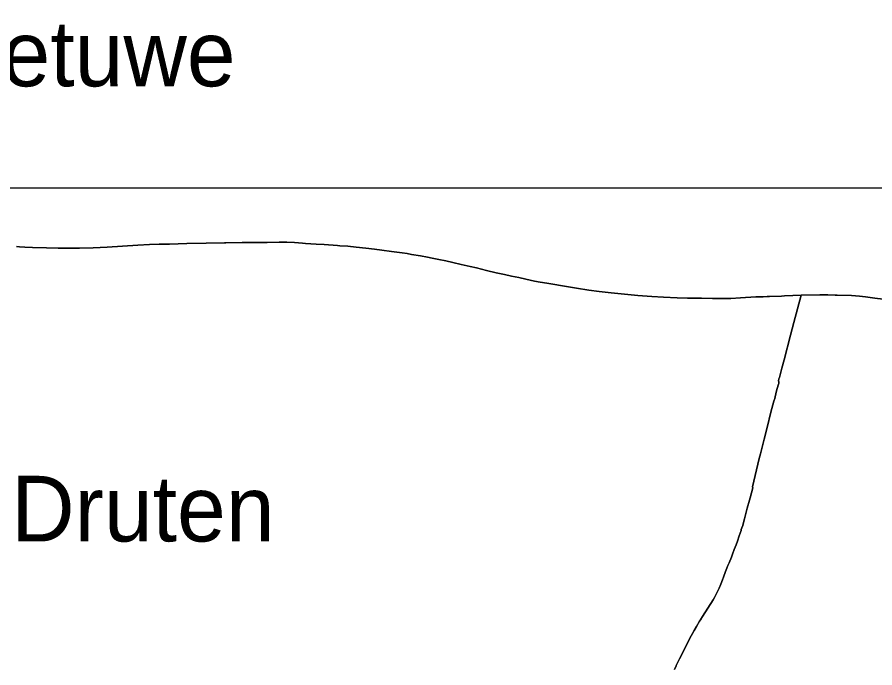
# Model space of a CAD drawing. Extents: x 113371 to 291721, y 393993 to 520143.
# Drawn here: x 169499 to 176035, y 431347 to 436303 of the extents above; entities that cross this region are included whole.
import ezdxf

# ---------------------------------------------------------------- set-up
doc = ezdxf.new("R2010")
doc.units = 0
for name, color, linetype in [('Boudingbox', 7, 'Continuous'), ('Default', 7, 'Continuous'), ('plaatsnamen', 7, 'Continuous')]:
    doc.layers.add(name, color=color, linetype=linetype)

msp = doc.modelspace()

# ---------------------------------------------------------------- linework, layer by layer
at = {"layer": 'Boudingbox'}
msp.add_line((177000, 435000), (164000, 435000), dxfattribs=at)
at = {"layer": 'Default'}
for points in [[(172504.745625, 434495.9625), (172471.995625, 434501.7225), (172433.555625, 434507.1525), (172350.655625, 434518.1225), (172278.425625, 434527.5125), (172221.665625, 434535.3625), (172156.345625, 434542.5625), (172082.175625, 434551.2025), (172019.735625, 434558.1425), (171958.345625, 434562.1025), (171939.345625, 434563.3225), (171838.765625, 434570.5125), (171778.715625, 434574.3425), (171697.205625, 434580.0125), (171674.285625, 434581.4725), (171612.385625, 434585.4125), (171554.745625, 434589.0725), (171495.255625, 434588.2825), (171403.815625, 434587.6825), (171361.415625, 434587.7225), (171212.845625, 434586.5725), (171089.845625, 434585.3025), (171078.245625, 434584.8525), (170938.375625, 434581.3825), (170791.285625, 434578.1325), (170660.135625, 434575.1825), (170581.985625, 434573.8525), (170506.225625, 434570.2825), (170418.085625, 434566.7525), (170185.095625, 434551.5725), (170077.115625, 434546.2025), (169974.555625, 434543.1825), (169811.185625, 434544.1725), (169721.305625, 434545.9225), (169615.485625, 434549.6925), (169557.505625, 434551.2625), (169515.485625, 434554.1825), (169493.465625, 434555.7025)], [(169493.465625, 434555.7025), (169515.485625, 434554.1825), (169557.505625, 434551.2625), (169615.485625, 434549.6925), (169721.305625, 434545.9225), (169811.185625, 434544.1725), (169974.555625, 434543.1825), (170077.115625, 434546.2025), (170185.095625, 434551.5725), (170418.085625, 434566.7525), (170506.225625, 434570.2825), (170581.985625, 434573.8525), (170660.135625, 434575.1825), (170791.285625, 434578.1325), (170938.375625, 434581.3825), (171078.245625, 434584.8525), (171089.845625, 434585.3025), (171212.845625, 434586.5725), (171361.415625, 434587.7225), (171403.815625, 434587.6825), (171495.255625, 434588.2825), (171554.745625, 434589.0725), (171612.385625, 434585.4125), (171674.285625, 434581.4725), (171697.205625, 434580.0125)], [(171697.205625, 434580.0125), (171778.715625, 434574.3425), (171838.765625, 434570.5125), (171939.345625, 434563.3225), (171958.345625, 434562.1025), (172019.735625, 434558.1425), (172082.175625, 434551.2025), (172156.345625, 434542.5625), (172221.665625, 434535.3625), (172278.425625, 434527.5125), (172350.655625, 434518.1225), (172433.555625, 434507.1525), (172471.995625, 434501.7225), (172504.745625, 434495.9625), (172573.835625, 434484.1625), (172626.265625, 434474.3525), (172662.475625, 434467.1225), (172712.205625, 434457.5925), (172765.095625, 434446.3025), (172817.985625, 434434.4025), (172882.745625, 434420.2025), (172906.485625, 434414.5725), (172952.025625, 434403.7925), (172999.065625, 434392.9025), (173076.765625, 434374.0125), (173150.555625, 434356.1325), (173212.755625, 434342.5125), (173265.655625, 434330.9125), (173321.995625, 434319.0425), (173376.395625, 434307.1525), (173441.455625, 434292.6525), (173485.475625, 434284.4325), (173536.605625, 434275.6325), (173582.185625, 434268.4225), (173653.715625, 434256.3825), (173760.935625, 434238.4925), (173856.465625, 434223.5925), (173935.505625, 434212.4425)], [(175010.355625, 434165.4825), (174937.215625, 434161.2925), (174923.275625, 434160.4925), (174882.065625, 434159.8325), (174798.225625, 434160.1125), (174714.375625, 434161.4425), (174606.525625, 434162.5025), (174528.685625, 434165.6125), (174424.895625, 434169.9525), (174334.745625, 434175.0025), (174229.605625, 434183.2225), (174128.225625, 434193.3625), (174026.085625, 434203.3625), (173935.505625, 434212.4425), (173856.465625, 434223.5925), (173760.935625, 434238.4925), (173653.715625, 434256.3825), (173582.185625, 434268.4225), (173536.605625, 434275.6325), (173485.475625, 434284.4325), (173441.455625, 434292.6525), (173376.395625, 434307.1525), (173321.995625, 434319.0425), (173265.655625, 434330.9125), (173212.755625, 434342.5125), (173150.555625, 434356.1325), (173076.765625, 434374.0125), (172999.065625, 434392.9025), (172952.025625, 434403.7925), (172906.485625, 434414.5725), (172882.745625, 434420.2025), (172817.985625, 434434.4025), (172765.095625, 434446.3025), (172712.205625, 434457.5925), (172662.475625, 434467.1225), (172626.265625, 434474.3525), (172573.835625, 434484.1625), (172504.745625, 434495.9625)], [(173935.505625, 434212.4425), (174026.085625, 434203.3625), (174128.225625, 434193.3625), (174229.605625, 434183.2225), (174334.745625, 434175.0025), (174424.895625, 434169.9525), (174528.685625, 434165.6125), (174606.525625, 434162.5025), (174714.375625, 434161.4425), (174798.225625, 434160.1125), (174882.065625, 434159.8325), (174923.275625, 434160.4925), (174937.215625, 434161.2925), (175010.355625, 434165.4825), (175128.895625, 434171.8125), (175184.525625, 434173.7825), (175215.075625, 434175.1725), (175232.685625, 434175.5225), (175323.655625, 434179.0625), (175345.575625, 434179.7125), (175473.135625, 434185.6725), (175616.195625, 434188.9525), (175639.965625, 434188.9425), (175677.435625, 434188.0225), (175732.735625, 434186.1425), (175741.635625, 434185.8425), (175747.495625, 434185.6425), (175858.615625, 434181.9825), (175918.185625, 434178.4625), (175965.025625, 434173.5125), (176034.775625, 434163.5225), (176098.005625, 434154.7125)], [(175052.745625, 432521.9825), (175055.435625, 432531.5225), (175063.195625, 432562.2125), (175079.905625, 432624.3625), (175084.295625, 432642.0225), (175104.675625, 432718.2225), (175103.605625, 432724.8625), (175154.735625, 432940.9225), (175164.195625, 432976.7225), (175179.775625, 433037.4225), (175192.775625, 433088.0525), (175215.645625, 433177.0925), (175243.775625, 433293.3725), (175266.735625, 433378.1425), (175271.965625, 433397.4625), (175284.445625, 433445.7625), (175291.945625, 433474.8325), (175300.875625, 433506.4125), (175303.015625, 433513.4025), (175303.715625, 433515.5825), (175304.345625, 433518.4125), (175304.045625, 433521.7125), (175303.355625, 433524.5925), (175299.845625, 433532.0025), (175304.465625, 433547.4825), (175307.795625, 433559.6025), (175327.005625, 433629.3625), (175343.685625, 433693.4225), (175392.745625, 433881.7425), (175417.995625, 433977.2125), (175473.135625, 434185.6725), (175345.575625, 434179.7125), (175323.655625, 434179.0625), (175232.685625, 434175.5225), (175215.075625, 434175.1725), (175184.525625, 434173.7825), (175128.895625, 434171.8125), (175010.355625, 434165.4825)], [(176098.005625, 434154.7125), (176034.775625, 434163.5225), (175965.025625, 434173.5125), (175918.185625, 434178.4625), (175858.615625, 434181.9825), (175747.495625, 434185.6425), (175741.635625, 434185.8425), (175732.735625, 434186.1425), (175677.435625, 434188.0225), (175639.965625, 434188.9425), (175616.195625, 434188.9525), (175473.135625, 434185.6725), (175417.995625, 433977.2125), (175392.745625, 433881.7425), (175343.685625, 433693.4225), (175327.005625, 433629.3625), (175307.795625, 433559.6025), (175304.465625, 433547.4825), (175299.845625, 433532.0025), (175303.355625, 433524.5925), (175304.045625, 433521.7125), (175304.345625, 433518.4125), (175303.715625, 433515.5825), (175303.015625, 433513.4025), (175300.875625, 433506.4125), (175291.945625, 433474.8325), (175284.445625, 433445.7625), (175271.965625, 433397.4625), (175266.735625, 433378.1425), (175243.775625, 433293.3725), (175215.645625, 433177.0925), (175192.775625, 433088.0525), (175179.775625, 433037.4225), (175164.195625, 432976.7225), (175154.735625, 432940.9225)], [(175154.735625, 432940.9225), (175103.605625, 432724.8625), (175104.675625, 432718.2225), (175084.295625, 432642.0225), (175079.905625, 432624.3625), (175063.195625, 432562.2125), (175055.435625, 432531.5225), (175052.745625, 432521.9825), (175041.625625, 432481.4525), (175026.375625, 432424.8025), (175025.685625, 432422.4725), (175024.845625, 432419.8825), (175018.295625, 432406.4525), (175017.685625, 432403.6025), (175017.565625, 432403.0625), (175017.705625, 432401.7025), (175015.375625, 432393.4325), (175002.145625, 432353.5125), (174987.925625, 432311.6325), (174977.895625, 432284.0525), (174964.365625, 432247.6225), (174951.495625, 432213.3425), (174942.525625, 432190.6325), (174924.115625, 432145.7625), (174915.855625, 432126.1425), (174907.745625, 432106.3625), (174897.825625, 432080.2525), (174883.145625, 432038.8325), (174874.845625, 432018.6125), (174861.685625, 431984.4025), (174849.815625, 431953.6025), (174831.835625, 431918.0525), (174812.115625, 431882.0625), (174802.185625, 431865.4325), (174722.195625, 431739.0325), (174716.935625, 431730.4425), (174713.885625, 431725.4425), (174706.195625, 431712.7725)], [(174561.565625, 431444.7425), (174613.035625, 431547.1325), (174636.615625, 431591.7325), (174645.665625, 431608.9025), (174657.885625, 431630.8925), (174675.075625, 431662.1425), (174699.565625, 431702.4225), (174706.195625, 431712.7725), (174713.885625, 431725.4425), (174716.935625, 431730.4425), (174722.195625, 431739.0325), (174802.185625, 431865.4325), (174812.115625, 431882.0625), (174831.835625, 431918.0525), (174849.815625, 431953.6025), (174861.685625, 431984.4025), (174874.845625, 432018.6125), (174883.145625, 432038.8325), (174897.825625, 432080.2525), (174907.745625, 432106.3625), (174915.855625, 432126.1425), (174924.115625, 432145.7625), (174942.525625, 432190.6325), (174951.495625, 432213.3425), (174964.365625, 432247.6225), (174977.895625, 432284.0525), (174987.925625, 432311.6325), (175002.145625, 432353.5125), (175015.375625, 432393.4325), (175017.705625, 432401.7025), (175017.565625, 432403.0625), (175017.685625, 432403.6025), (175018.295625, 432406.4525), (175024.845625, 432419.8825), (175025.685625, 432422.4725), (175026.375625, 432424.8025), (175041.625625, 432481.4525), (175052.745625, 432521.9825)], [(174706.195625, 431712.7725), (174699.565625, 431702.4225), (174675.075625, 431662.1425), (174657.885625, 431630.8925), (174645.665625, 431608.9025), (174636.615625, 431591.7325), (174613.035625, 431547.1325), (174561.565625, 431444.7425), (174546.935625, 431415.6325), (174544.125625, 431410.0625), (174521.955625, 431365.9525), (174520.315625, 431362.4125), (174507.825625, 431335.3125)], [(174507.825625, 431335.3125), (174520.315625, 431362.4125), (174521.955625, 431365.9525), (174544.125625, 431410.0625), (174546.935625, 431415.6325), (174561.565625, 431444.7425)]]:
    msp.add_lwpolyline(points, dxfattribs=at)

# ---------------------------------------------------------------- texts
at = {"layer": 'plaatsnamen'}
for s, p in [('Neder-Betuwe', (166889.829453, 435776.231667)), ('Druten', (169454.041144, 432309.738609))]:
    msp.add_text(s, height=500, dxfattribs=at).set_placement(p)

doc.saveas('drawing.dxf')
